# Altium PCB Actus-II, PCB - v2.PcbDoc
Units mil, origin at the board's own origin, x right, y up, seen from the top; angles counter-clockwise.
Board outline 1300 x 1300 mil, 2 copper layers (Top Layer, Bottom Layer), stack 65.8 mil thick; 22 components, 31 nets, 85 pads, 25 vias.
Unrouted connection lines stored in the file: 3.
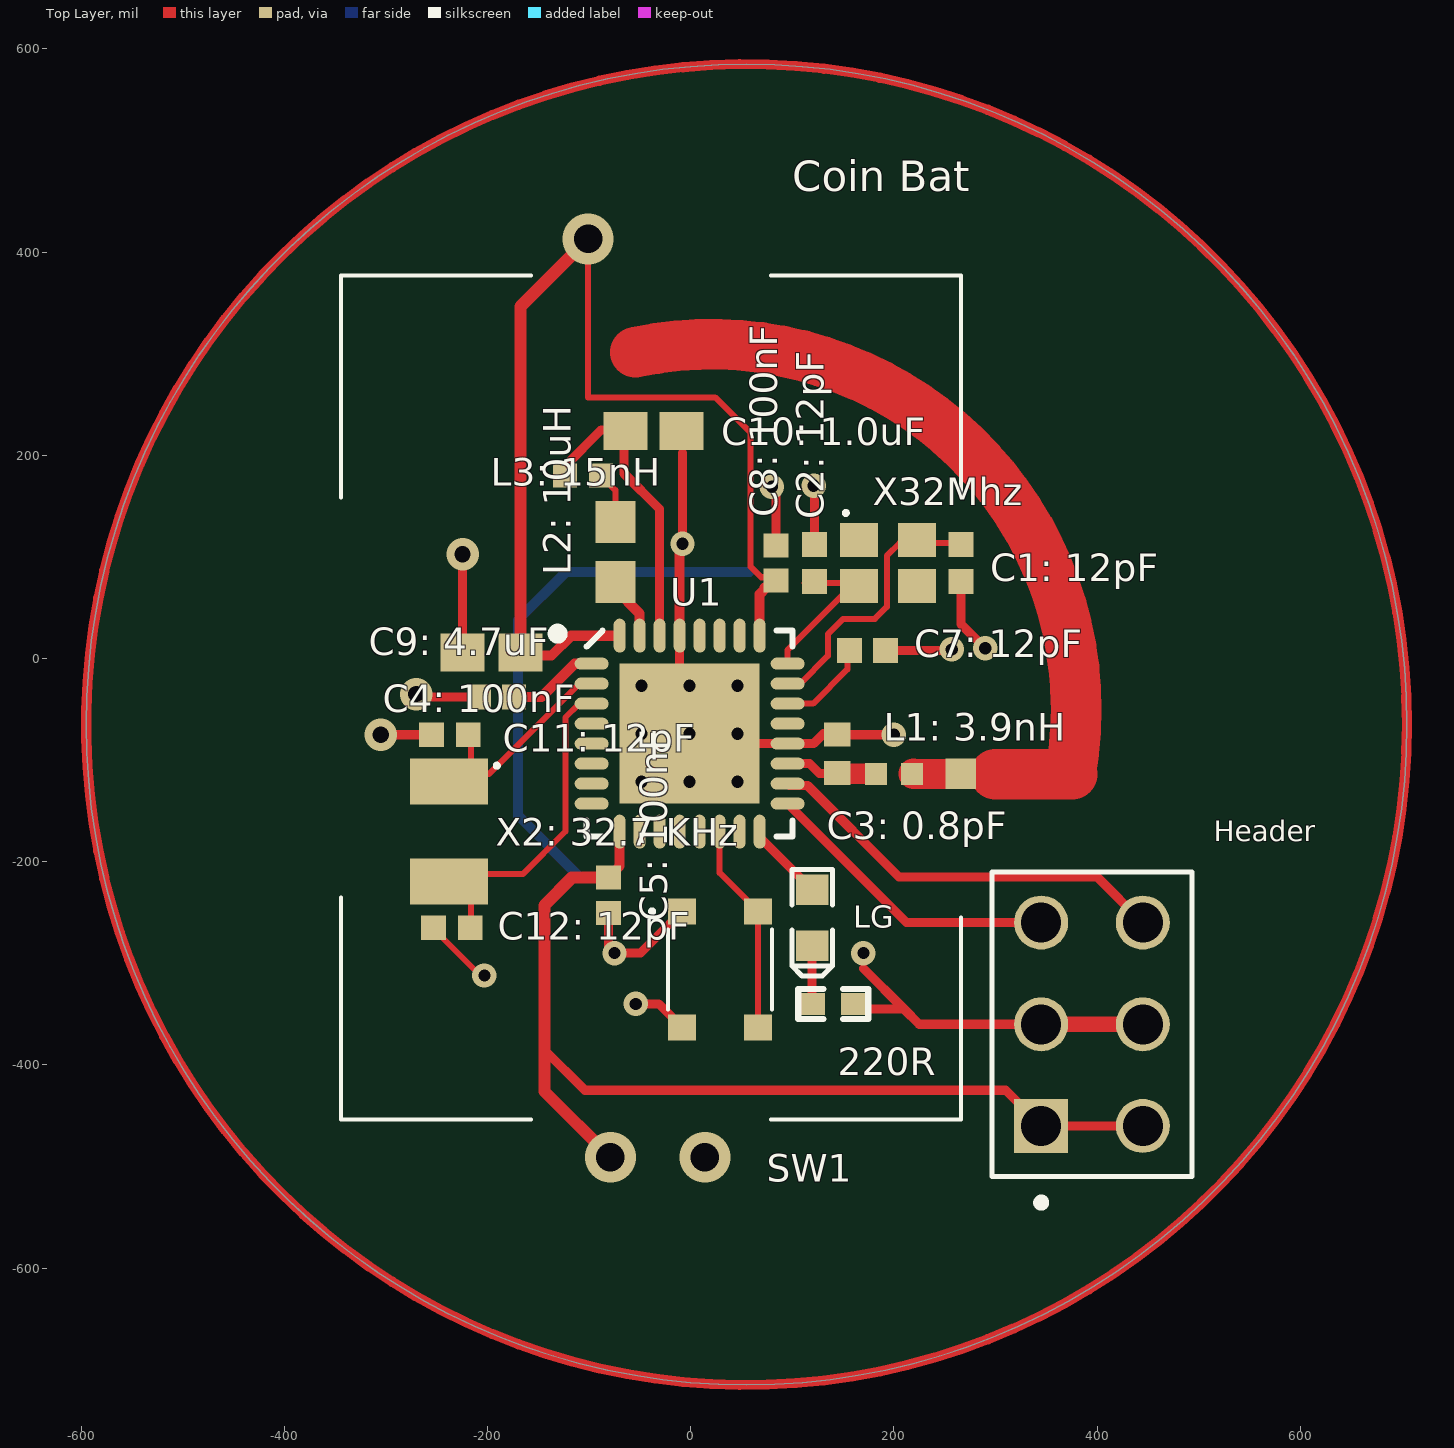
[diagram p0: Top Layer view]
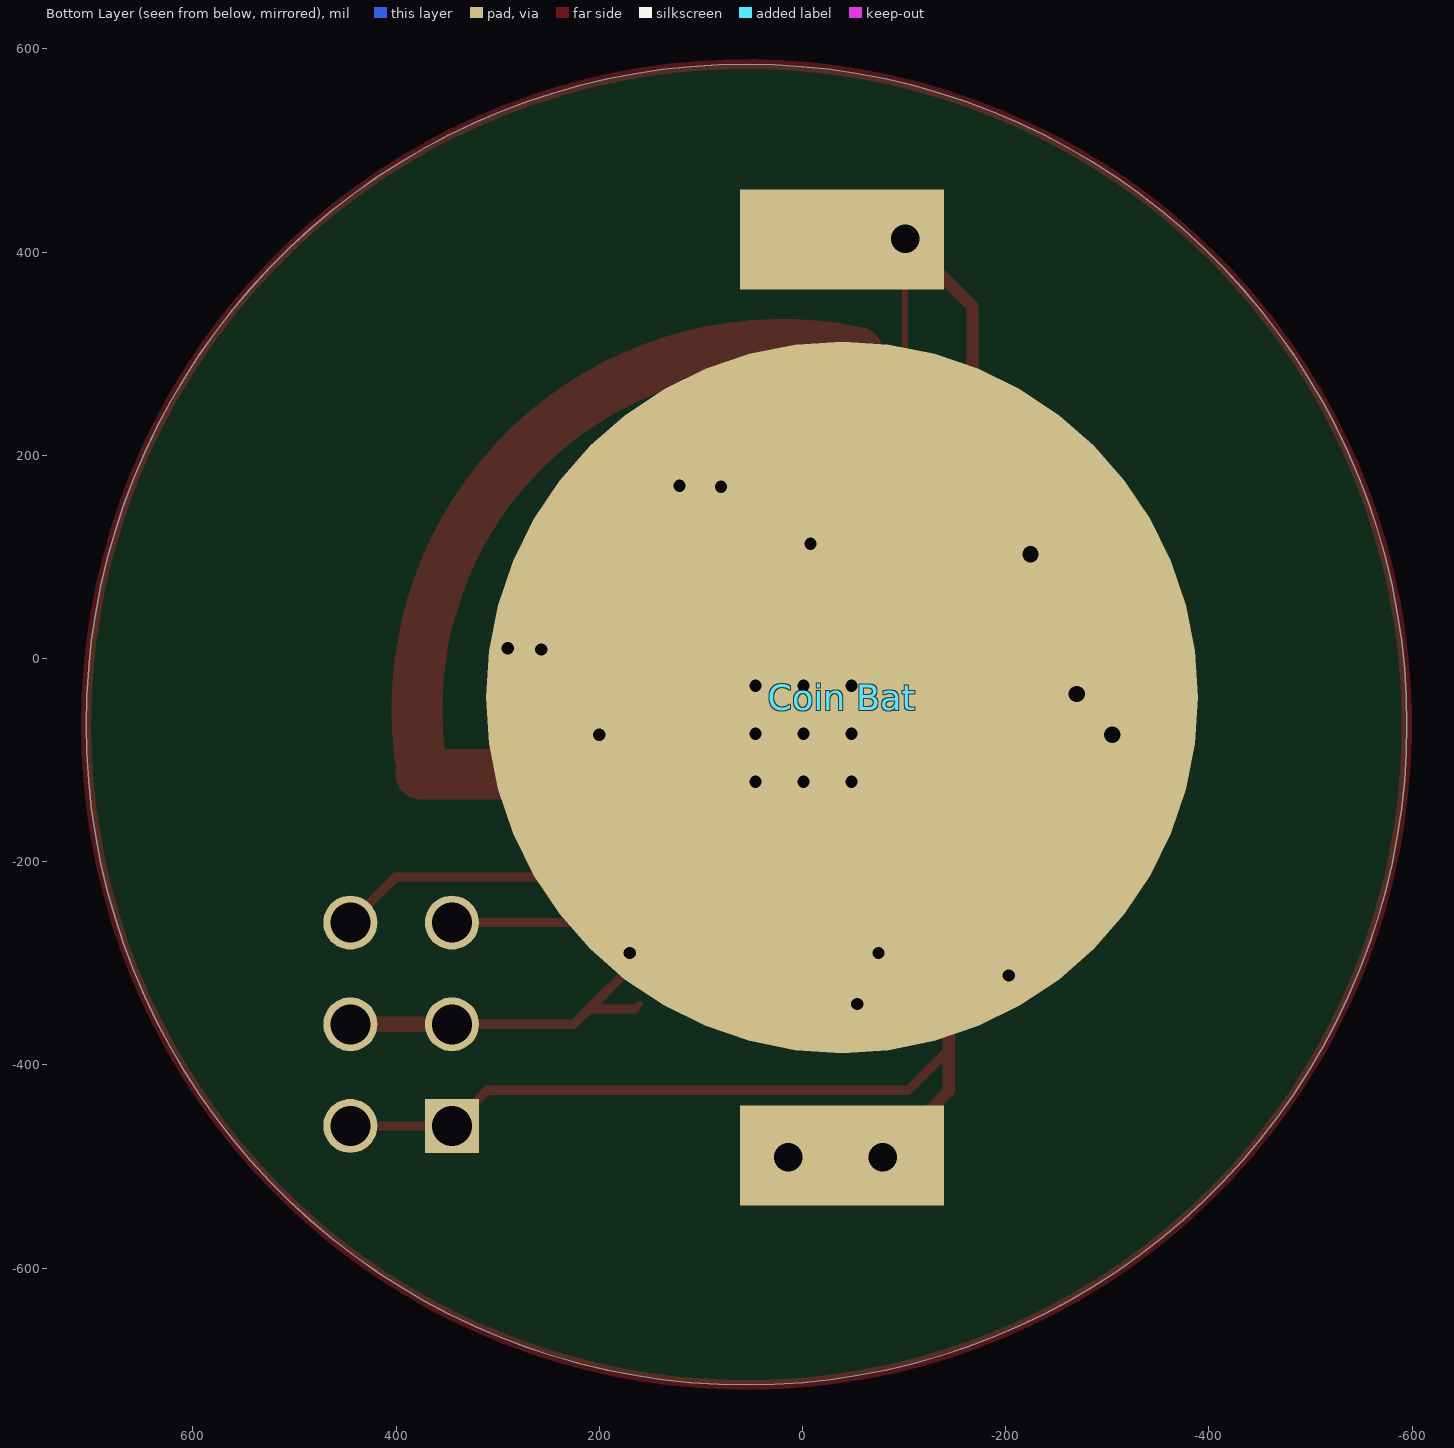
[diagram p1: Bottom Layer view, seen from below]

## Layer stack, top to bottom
Top Solder: solder mask 0.4, Solder Resist, Dk 3.5
Top Layer: signal copper 1.4
Dielectric1: core 63, FR-4, Dk 4.8
Bottom Layer: signal copper 1.4
Bottom Solder: solder mask 0.4, Solder Resist, Dk 3.5

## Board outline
55,-715 cw(c55,-65) -595,-65 cw(c55,-65) 55,585 cw(c55,-65) 705,-65 cw(c55,-65)

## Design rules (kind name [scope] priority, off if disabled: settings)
Clearance Polygon_ANT [(InNamedPolygon('Top_Layer-GND')) or (InNamedPolygon('Bottom_Layer-GND')) vs InNet('RF')] p1: gap=5 ignorepadtopadclearanceinfootprint=FALSE except(0: Arc-Hole Track-Hole SMDPad-Hole THPad-Hole Via-Hole Fill-Hole Poly-Hole Region-Hole Text-Hole)
Clearance Polygon [(InNamedPolygon('Top_Layer-GND')) or (InNamedPolygon('Bottom_Layer-GND'))] p2: gap=10 ignorepadtopadclearanceinfootprint=FALSE except(0: Arc-Hole Track-Hole SMDPad-Hole THPad-Hole Via-Hole Fill-Hole Poly-Hole Region-Hole Text-Hole)
Clearance [All] p3: gap=6 ignorepadtopadclearanceinfootprint=FALSE except(0: Arc-Hole Track-Hole SMDPad-Hole THPad-Hole Via-Hole Fill-Hole Poly-Hole Region-Hole Text-Hole)
ComponentClearance [All] p1 off: gap=10 collisioncheckmode=3 verticalgap=10 showdistances=FALSE
FabricationTestPointUsage TestPointUsage [All] p1: valid=0 allowmultiple=FALSE
FabricationTestpoint Testpoint [All] p1: side=3 testpointundercomponent=TRUE minsize=40 maxsize=100 preferedsize=60 minholesize=0 maxholesize=40 preferedholesize=32 testpointgrid=1 allowsidetop=TRUE allowsidebottom=TRUE usegrid=TRUE gridtolerance=0.01
Height [All] p1 off: minheight=0 maxheight=1000 prefheight=500
HoleSize [All] p1: absolutevalues=TRUE maxlimit=160 minlimit=12 maxpercent=80.000 minpercent=20.000
MinimumAnnularRing [All] p1 off: minimumring=6
PolygonConnect PolygonConnect_1 [isVia and innet(gnd)] p1: connectstyle=Direct reliefconductorwidth=10 reliefentries=4 polygonreliefangle="90 Angle" airgapwidth=10
PolygonConnect [All] p2: connectstyle=Relief reliefconductorwidth=10 reliefentries=4 polygonreliefangle="90 Angle" airgapwidth=10
RoutingVias [All] p1: holewidth=16 width=32 viastyle="Through Hole" minholewidth=10 minwidth=10 maxholewidth=28 maxwidth=50
SilkToSolderMaskClearance SilkscreenOverComponentPads [IsPad] p1: minsilkscreentomaskgap=10 clearancetoexposedcopper=TRUE
SolderMaskExpansion [All] p1: expansion=3
Width [All] p1: maxlimit=100 minlimit=6 preferedwidth=6
24 further rules are at their usual default settings.

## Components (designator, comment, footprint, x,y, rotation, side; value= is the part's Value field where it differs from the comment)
220R "RLEDG" RLEDG 140.31,-340 r0 top
"C1: 12pF" "CC0402GRNPO9BN120" CC0402GRNPO9BN120 266,94 r270 top
"C2: 12pF" "CC0402GRNPO9BN120" CC0402GRNPO9BN120 122,94 r90 top
"C3: 0.8pF" "201R07S0R8AV4T" 201R07S0R8AV4T 144.31,-93.69 r90 top
"C4: 100nF" "CC0402KRX7R7BB104" CC0402KRX7R7BB104 -191,-38 r180 top
"C5: 100nF" "CC0402KRX7R7BB104" CC0402KRX7R7BB104 -81,-233 r270 top
"C7: 12pF" "C0402C101J5GAC7411" C0402C101J5GAC7411 174,8 r0 top
"C8: 100nF" "CC0402KRX7R7BB104" CC0402KRX7R7BB104 84,94 r90 top
"C9: 4.7uF" "JMK107BJ475KA-T" JMK107BJ475KA-T -196,6 r180 top
"C10: 1.0uF" "CC0603KRX7R7BB105" CC0603KRX7R7BB105 -36.44,224 r0 top
"C11: 12pF" "CC0402GRNPO9BN120" CC0402GRNPO9BN120 -237,-75 r0 top
"C12: 12pF" "CC0402GRNPO9BN120" CC0402GRNPO9BN120 -235,-265 r0 top
"Coin Bat" "Bat" Bat -40,-40.21 r90 top
Header "Header" Header 395,-360 r90 top (schematic designator "6 Pos Header")
"L1: 3.9nH" "LQP15MN3N9B02D" LQP15MN3N9B02D 200.31,-113.69 r0 top
"L2: 10uH" "MLZ1608N100LT000" MLZ1608N100LT000 -74,105 r90 top
"L3: 15nH" "HK100515NJ-T" HK100515NJ-T -106,180 r180 top
LG "LEDG" LEDG 119.55,-255 r90 top
SW1 "KMT021 NGJ LHS" Switch 29,-306 r270 top
U1 "nRF52810-QCAA" Nordic_QFN50P500X500X90-33N -1,-74 r0 top locked
"X2: 32.7 KHz" "FC-135R 32.7680KA-AC3" "FC-135R 32.7680KA-AC3" -238,-170.5 r270 top
X32Mhz "Q22FA12800025" Q22FA12800025 194,94 r0 top

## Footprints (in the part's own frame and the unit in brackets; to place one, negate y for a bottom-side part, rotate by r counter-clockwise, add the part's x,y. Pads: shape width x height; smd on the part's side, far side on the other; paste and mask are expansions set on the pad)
201R07S0R8AV4T [mm] "C3, 0.8pF, 0402, Johanson Dielectrics (Dimensiones no especificadas en datasheet, medidas tomadas de Mouser)"
  rect 0.6x0.66 smd: 1(-0.48,0) 2(0.48,0)
  body extent -0.51,-0.26 0.51,0.25, height 0.64
Bat [mm]
  rect 2.5x5.1 smd far side: 1(11.501,-0.025) 2(-11.399,-0.025)
  round 17.8 smd far side mask+0.102: 3(0.051,-0.025)
  silkscreen extent -10.5,-7.78 10.6,7.72, body extent -11.52,-9.02 11.72,8.69, height 4.08
C0402C101J5GAC7411 [mm] "C7: 100 pF, 0402, KEMET"
  rect 0.62x0.62 smd: 1(-0.45,0) 2(0.45,0)
  body extent -0.53,-0.28 0.53,0.27, height 0.55
CC0402GRNPO9BN120 [mm] "C1, C2, C11, C12: 12pF, 0402, Yageo"
  rect 0.62x0.62 smd: 1(-0.46,0) 2(0.46,0)
  body extent -0.53,-0.28 0.53,0.27, height 0.55
CC0402KRX7R7BB104 [mm] "C4, C5, C8: 100nF (0.1uF), 0402, Yageo"
  rect 0.6x0.62 smd: 1(-0.44,0) 2(0.44,0)
  body extent -0.53,-0.28 0.53,0.27, height 0.55
CC0603KRX7R7BB105 [mm] "C10: 1.0uF, 0603, Yageo"
  rect 1.1x0.95 smd: 1(-0.7,0) 2(0.7,0)
  body extent -0.85,-0.45 0.85,0.45, height 0.9
"FC-135R 32.7680KA-AC3" [mm] "X2: 32.7680KHZ, XTAL_3215, EPSON"
  rect 1.15x1.95 smd: 1(-1.25,0) 2(1.25,0)
  silkscreen extent -1.7,1.15 -1.6,1.25, body extent -1.65,-0.8 1.65,0.8, height 0.9
Header [mm]
  rect 1.35x1.35 hole 1: 1(-2.54,1.27)
  round 1.35 hole 1: 2(-2.54,-1.27) 3(0,1.27) 4(0,-1.27) 5(2.54,1.27) 6(2.54,-1.27)
  silkscreen extent -4.56,-2.5 3.81,2.5, body extent -3.81,-2.54 3.81,2.54, height 9.5
HK100515NJ-T [mm] "L3: 15nH, 0402, Taiyo Yuden"
  rect 0.6x0.6 smd: 1(-0.45,0) 2(0.45,0)
  body extent -0.53,-0.28 0.53,0.27, height 0.55
JMK107BJ475KA-T [mm] "C9: 4.7uF, 0603, Taiyo Yuden"
  rect 1.1x0.95 smd: 1(-0.725,0) 2(0.725,0)
  body extent -0.85,-0.45 0.85,0.45, height 0.9
LEDG [mil]
  rect 30x32 smd: 1(-27.5,0) 2(27.5,0)
  silkscreen extent -58,-20 48,20, body extent -32,-16 32,16, height 24
LQP15MN3N9B02D [mm] "L1: 3.9 nH, 0402 (1005 metric), Murata Electronics"
  rect 0.55x0.55 smd: 1(-0.45,0) 2(0.45,0)
  body extent -0.55,-0.2 0.55,0.2, height 0.45
MLZ1608N100LT000 [mm] "L2: 10 uH, 0603 (1608 metric), TDK"
  rect 1.05x1 smd: 1(-0.75,0) 2(0.75,0)
  body extent -0.88,-0.48 0.87,0.47, height 0.95
Nordic_QFN50P500X500X90-33N [mm] "QFN32 5x5x0.85mm, 0.5mm pitch - Medium Density"
  oval 0.85x0.3 smd mask+0.076: 1(-2.45,1.75) 2(-2.45,1.25) 3(-2.45,0.75) 4(-2.45,0.25) 5(-2.45,-0.25) 6(-2.45,-0.75) 7(-2.45,-1.25) 8(-2.45,-1.75) 17(2.45,-1.75) 18(2.45,-1.25) 19(2.45,-0.75) 20(2.45,-0.25) 21(2.45,0.25) 22(2.45,0.75) 23(2.45,1.25) 24(2.45,1.75)
  oval 0.3x0.85 smd mask+0.076: 9(-1.75,-2.45) 10(-1.25,-2.45) 11(-0.75,-2.45) 12(-0.25,-2.45) 13(0.25,-2.45) 14(0.75,-2.45) 15(1.25,-2.45) 16(1.75,-2.45) 25(1.75,2.45) 26(1.25,2.45) 27(0.75,2.45) 28(0.25,2.45) 29(-0.25,2.45) 30(-0.75,2.45) 31(-1.25,2.45) 32(-1.75,2.45)
  rect 3.5x3.5 smd: 33(0,0)
  silkscreen extent -3.42,-2.57 2.57,2.62, body extent -2.5,-2.5 2.5,2.5, height 0.9
Q22FA12800025 [mm] "X1: 32MHz, XTAL_2016, EPSON"
  rect 0.95x0.85 smd: #1(-0.725,-0.575) #2(0.725,-0.575) #3(0.725,0.575) #4(-0.725,0.575)
  silkscreen extent -1.1,1.2 -1,1.3, body extent -1.05,-0.85 1.05,0.85, height 0.5
RLEDG [mm]
  rect 0.6x0.55 smd: 1(-0.5,0) 2(0.5,0)
  silkscreen extent -0.87,-0.38 0.88,0.38, body extent -0.5,-0.25 0.5,0.25, height 0.3
Switch [mm] "Switch"
  rect 0.65x0.7 smd: 1(-1.45,-0.95) 2(1.45,-0.95) 3(1.45,0.95) 4(-1.45,0.95)
  silkscreen extent -1.5,-1.75 1,1.3

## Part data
"C1: 12pF" "C2: 12pF" "C11: 12pF" "C12: 12pF": "C1, C2, C11, C12:  12pF, 0402, Yageo"
"C3: 0.8pF": "C3: 0.8pF, 0402, Johanson Dielectrics"
"C4: 100nF" "C5: 100nF" "C8: 100nF": "C4, C5, C8 : 100nF (0.1uF), 0402, Yageo"
"C7: 12pF": "C7: 100 pF, 0402, KEMET"
"C9: 4.7uF": "C9: 4.7uF, 0603, Taiyo Yuden"
"C10: 1.0uF": "C10: 1.0uF, 0603, Yageo"
"L1: 3.9nH": "L1: 3.9 nH, 0402 (1005 metric), Murata Electronics"
"L2: 10uH": "L2: 10 uH, 0603 (1608 metric), TDK"
"L3: 15nH": "L3: 15nH, 0402, Taiyo Yuden"
SW1: "Micro-Switch"
U1: "Multi-protocol Bluetooth Low Energy, ANT and 2.4GHz proprietary system-on-chip", Manufacturer="Nordic Semiconductor"
"X2: 32.7 KHz": "X2: 32.7680KHZ, XTAL_3215, EPSON"
X32Mhz: "X1: 32MHz, XTAL_2016, EPSON"

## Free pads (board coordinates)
  rect 30x30 smd: 0(266.06,-113.43)

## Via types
v1: diameter 24, hole 12, Top Layer to Bottom Layer, tented both sides, 9 vias
v2: diameter 24, hole 12, Top Layer to Bottom Layer, tented bottom, 9 vias
v3: diameter 50, hole 28, Top Layer to Bottom Layer, 3 vias
v4: diameter 32, hole 16, Top Layer to Bottom Layer, 3 vias
v5: diameter 24/24 (per signal layer), hole 12, Top Layer to Bottom Layer, tented both sides, 1 vias

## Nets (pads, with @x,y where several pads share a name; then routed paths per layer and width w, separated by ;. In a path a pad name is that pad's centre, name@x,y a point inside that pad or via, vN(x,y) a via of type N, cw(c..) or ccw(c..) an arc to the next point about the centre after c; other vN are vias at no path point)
DEC1: "C4: 100nF.1" U1.1 | length 83.5
  Top Layer w10: -167.32,-38 -147,-38 -114.1,-5.1 U1.1
DEC2: U1.21
DEC3: "C7: 12pF.1" U1.22 | length 92.5
  Top Layer w6: U1.22 120.53,-44.47 154.31,-10.69 154.31,9
DEC4: "C10: 1.0uF.1" "L3: 15nH.2" U1.30 | length 301.1
  Top Layer w6: -123.72,180 -123.72,189.28
  Top Layer w9: -126,180.57 -124.72,179.28 ; -123.72,189.28 -88,225 -65.57,225 -65.57,182.05 -30.53,147 U1.30
GND: 220R.2 "C1: 12pF.2" "C2: 12pF.2" "C3: 0.8pF.2" "C4: 100nF.2" "C5: 100nF.2" "C7: 12pF.2" "C8: 100nF.2" "C9: 4.7uF.2" "C10: 1.0uF.2" "C11: 12pF.1" "C12: 12pF.1" "Coin Bat.3" Header.3 Header.4 SW1.1 SW1.2 U1.20 U1.29 U1.33 | length 2081.3
  Top Layer w6: v4(-270,-35) v4@-267,-38 ; -253.11,-265 -253.11,-265.92 -207.03,-312 v1(-203,-312) ; v1@-81,-284 v1(-75,-290) ; -73.68,-251 -72,-249.32 ; v1@-10.84,110.16 v1(-8,113) ; -8.88,203 -8,202.12 ; v1(80,169) v1@84,165 ; 120,114.11 122,112.11 ; v5(121,170) 120,169 v5@122,167 ; 144.31,-74.79 144.53,-75 ; 220R.2 220R.2@165,-345 ; 170,-305 v1(170,-290) ; v1@256,8 v1(257,9)
  Top Layer w9: v4(-305,-75) -255.11,-75 ; v4@-267,-38 -208.32,-38 ; -224.54,3 v4(-224.54,102.54) ; v1@-81,-284 -81,-250.32 ; v1(-75,-290) -49.49,-290 SW1.1 ; v1(-54,-340) -31.49,-340 SW1.2 ; U1.29 -10.84,-64.16 v2(-1,-74) ; v1(-8,113) -8,202.12 ; U1.33@26.56,-80.89 29.51,-83.84 U1.20 120.89,-83.84 130.73,-74 144.32,-74 ; 84,111.32 v1@84,165 ; 122,112.11 v5@122,167 ; 144.32,-76.35 144.63,-76.35 ; 144.53,-75 v1(200,-75) ; 220R.2@165,-345 210,-345 ; 170,-305 210,-345 ; 191.72,8 v1@256,8 ; 266,75.89 266,34 v1(290,10) ; Header.3 225,-360 210,-345
  Top Layer w10: U1.29 v1@-10.84,110.16
  Top Layer w15: Header.3 Header.4
  Bottom Layer w10: -109,-215.32 -170,-154.32 -170,38 -123,85 58,85
  other v2: -48.24,-121.24 -1,-121.24 46.24,-121.24 -48.24,-74 46.24,-74 -48.24,-26.76 -1,-26.76 46.24,-26.76
Net220R_1: 220R.1 LG.1 | length 57.9
  Top Layer w6: 220R.1@119.55,-338.92 220R.1
  Top Layer w9: 220R.1@119.55,-338.92 LG.1
"NetC3: 0.8pF_1": "C3: 0.8pF.1" "L1: 3.9nH.1" U1.19 | length 88.6
  Top Layer w9: U1.19 117.11,-103.53 126.95,-113.37 144.32,-113.37 ; 144.32,-115.72 144.63,-115.72
  Top Layer w20: 144.31,-113.53 179.63,-113.53
"NetL2: 10uH_1": "L2: 10uH.1" U1.31 | length 55.3
  Top Layer w10: -74,67.94 -50.21,44.16 U1.31
"NetL2: 10uH_2": "L2: 10uH.2" "L3: 15nH.1" | length 62.3
  Top Layer w6: -88.28,180 -74,165.72 -74,134.53
  Top Layer w10: -74,123.57 -74,134.53
NetSW1_3: SW1.3 SW1.4 U1.14 | length 208.3
  Top Layer w6: U1.14 28.53,-211.04 SW1.4 SW1.3
P0.00/XL1: "C11: 12pF.2" "X2: 32.7 KHz.1" U1.2 | length 207.4
  Top Layer w6: -216.32,-73 -216.32,-106.1 -224,-113.79 -198.68,-113.79 -109.68,-24.79 U1.2
P0.01/XL2: "C12: 12pF.2" "X2: 32.7 KHz.2" U1.3 | length 321.3
  Top Layer w6: -216.32,-253 -216.32,-230.9 -235,-212.21 -165.21,-212.21 -123.19,-170.19 -123.19,-57.98 -109.68,-44.47 U1.3
P0.04/AIN2: U1.4
P0.05/AIN3: U1.5
P0.06: U1.6
P0.09: U1.7
P0.12: U1.10
P0.14: U1.11
P0.15: U1.12
P0.16: U1.13
P0.21: LG.2 U1.16 | length 78.4
  Top Layer w6: U1.16@67.9,-175.85 U1.16
  Top Layer w9: U1.16@67.9,-175.85 LG.2
P0.25: U1.26
P0.28/AIN4: U1.27
P0.30/AIN6: U1.28
RF: "L1: 3.9nH.2" pad.0 | length 824.2
  Top Layer w6: pad.0@265.81,-113.69 pad.0
  Top Layer w30: 219.33,-113.43 pad.0@266.06,-113.69
  Top Layer w50: -54.19,301.49 cw(c20.45,-49.66) 374,-112 ; 300,-114 375.36,-114
SWDCLK: Header.5 U1.17 | length 298
  Top Layer w9: U1.17 212.56,-260 Header.5
SWDIO: Header.6 U1.18 | length 406.2
  Top Layer w6: U1.18 U1.18@97.24,-125
  Top Layer w9: U1.18@97.24,-125 115,-125 205,-215 400,-215 Header.6
VDD_NRF: "C5: 100nF.1" "C8: 100nF.1" "C9: 4.7uF.1" Header.1 Header.2 U1.9 U1.25 U1.32 | length 2109.6
  Top Layer w6: v3(-101,413) -101,257 24,257 59,222 59,90.51 69.51,80 80.68,80 84,76.68
  Top Layer w9: -144,-385 -104,-425 310,-425 Header.1 Header.2
  Top Layer w10: -170,4.43 -171.43,3 -137,3 -117.54,22.46 U1.32 ; -81,-215.32 -69.9,-204.21 U1.9 ; U1.25 67.9,63.21 74.68,70 73,70
  Top Layer w12: -167.46,6 -167.46,346.54 v3(-101,413) ; -81,-215.68 -116.68,-215.68 -144,-243 -144,-385 -144,-426 v3(-79,-491)
  other v3: 14,-491
VTG: "Coin Bat.1" "Coin Bat.2"
XC1: "C1: 12pF.1" U1.23 X32Mhz.#3 | length 257.8
  Top Layer w6: U1.23 107.68,-24.79 135.08,2.61 135.08,23.93 150.15,39 181.26,39 193.16,50.9 193.16,101.16 205.68,113.68 254,113.68
XC2: "C2: 12pF.1" U1.24 X32Mhz.#1 | length 147.2
  Top Layer w6: U1.24 95.46,8.46 155.46,68.46 X32Mhz.#1@155.46,68.52 ; 112,74.31 114,74.31 149.66,74.31 X32Mhz.#1@155.46,68.52 ; X32Mhz.#1@155.46,71.36 X32Mhz.#1@155.46,68.52
pads on no net: U1.8 U1.15 X32Mhz.#2 X32Mhz.#4
copper on no net: | length 4084.1
  Top Layer w10: 705,-65 ccw(c55,-65) 705,-65

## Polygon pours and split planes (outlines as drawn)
no net on Top Layer "Top Layer-No Net" (solid, pour order 4): 150,190
no net on Top Layer "Top Layer-No Net 1" (solid, pour order 2): 175,185

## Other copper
Top Layer:
  pour cut-out: 224,-135.03 116,-135.03 116,-44 224,-44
